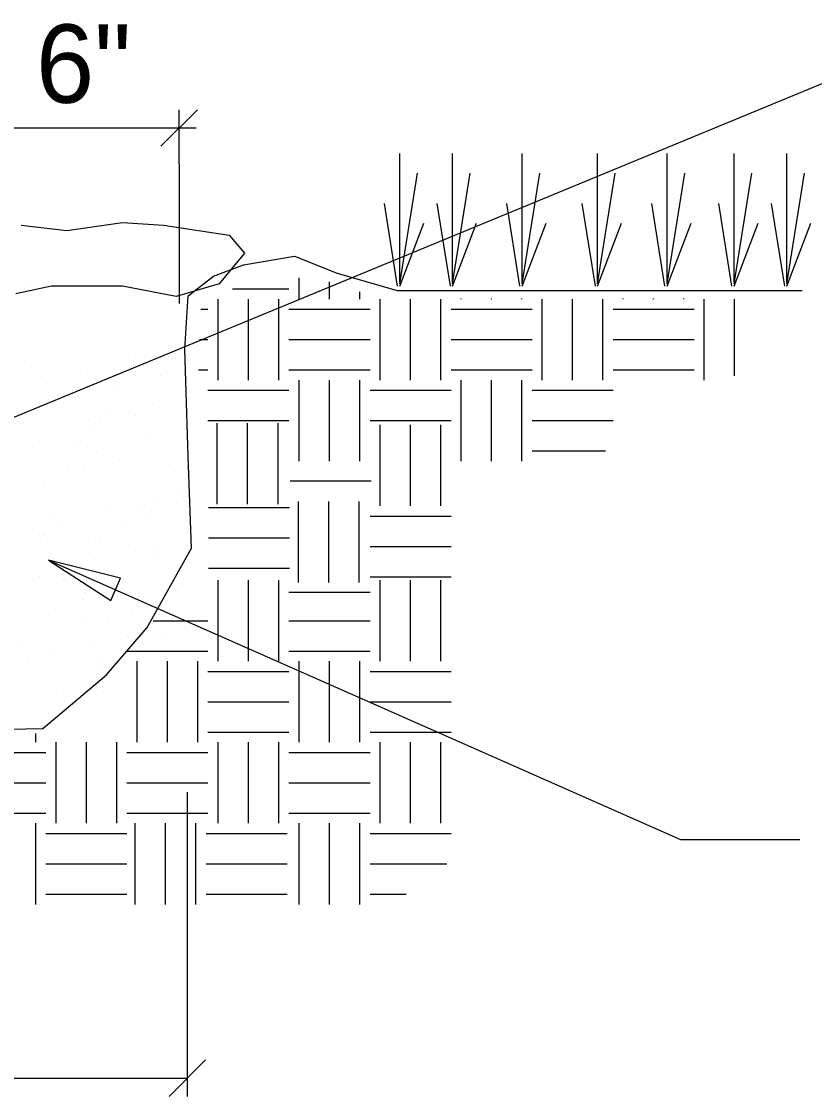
# Model space of a CAD drawing. Extents: x 10082 to 10186, y 10014 to 10052.
# Drawn here: x 10140.32 to 10147.41, y 10037.57 to 10047.18 of the extents above; entities that cross this region are included whole.
import ezdxf

# ---------------------------------------------------------------- set-up
doc = ezdxf.new("R2010")
doc.units = 0
for name, color, linetype in [('Default', 7, 'Continuous'), ('G-DETL-LINE', 7, 'Continuous'), ('G-DETL-OTLN', 7, 'Continuous'), ('G-DETL-PATT', 7, 'Continuous'), ('G-DETL-TEXT', 7, 'Continuous')]:
    doc.layers.add(name, color=color, linetype=linetype)

msp = doc.modelspace()

# ---------------------------------------------------------------- linework, layer by layer
at = {"layer": 'Default'}
for p, q in [((10148.8255, 10047.185), (10138.6003, 10042.9639)), ((10141.5679, 10046.0695), (10141.8951, 10046.3967)), ((10141.7315, 10045.9132), (10141.7315, 10046.3967)), ((10141.7315, 10045.9132), (10141.7315, 10044.6626)), ((10140.5637, 10042.3692), (10146.2107, 10039.8724)), ((10141.8034, 10040.2946), (10141.8034, 10037.5748)), ((10146.2107, 10039.8724), (10147.2796, 10039.8724)), ((10141.6398, 10037.5748), (10141.967, 10037.902)), ((10131.4864, 10037.7384), (10141.8034, 10037.7384))]:
    msp.add_line(p, q, dxfattribs=at)
msp.add_lwpolyline([(10139.3889, 10046.2331), (10141.8813, 10046.2331)], dxfattribs=at)
msp.add_lwpolyline([(10141.1194, 10042.009), (10141.2062, 10042.2087), (10140.5637, 10042.3692)], close=True, dxfattribs=at)
at = {"layer": 'G-DETL-LINE'}
for p, q in [((10143.7023, 10044.8565), (10143.7023, 10046.0061)), ((10144.1749, 10044.8565), (10144.1749, 10046.0061)), ((10144.7969, 10044.8565), (10144.7969, 10046.0061)), ((10145.4714, 10044.8565), (10145.4714, 10046.0061)), ((10146.0933, 10044.8565), (10146.0933, 10046.0061)), ((10146.6911, 10044.8565), (10146.6911, 10046.0061)), ((10147.1636, 10044.8565), (10147.1636, 10046.0061)), ((10143.7023, 10044.839), (10143.8599, 10045.8306)), ((10144.1749, 10044.839), (10144.3324, 10045.8306)), ((10144.7969, 10044.839), (10144.9544, 10045.8306)), ((10145.4714, 10044.839), (10145.6289, 10045.8306)), ((10146.0933, 10044.839), (10146.2509, 10045.8306)), ((10146.6911, 10044.839), (10146.8486, 10045.8306)), ((10147.1636, 10044.839), (10147.3212, 10045.8306)), ((10143.6821, 10044.8185), (10143.565, 10045.5586)), ((10144.1547, 10044.8185), (10144.0376, 10045.5586)), ((10144.7767, 10044.8185), (10144.6595, 10045.5586)), ((10145.4512, 10044.8185), (10145.334, 10045.5586)), ((10146.0731, 10044.8185), (10145.956, 10045.5586)), ((10146.6709, 10044.8185), (10146.5538, 10045.5586)), ((10147.1434, 10044.8185), (10147.0263, 10045.5586)), ((10143.7023, 10044.8185), (10143.9164, 10045.3831)), ((10144.1749, 10044.8185), (10144.3889, 10045.3831)), ((10144.7969, 10044.8185), (10145.0109, 10045.3831)), ((10145.4714, 10044.8185), (10145.6854, 10045.3831)), ((10146.0933, 10044.8185), (10146.3074, 10045.3831)), ((10146.6911, 10044.8185), (10146.9052, 10045.3831)), ((10147.1636, 10044.8185), (10147.3777, 10045.3831))]:
    msp.add_line(p, q, dxfattribs=at)
at = {"layer": 'G-DETL-OTLN'}
for points in [[(10140.3195, 10045.3656), (10140.7269, 10045.3179), (10141.2242, 10045.3873), (10141.5897, 10045.3656), (10142.1768, 10045.2745), (10142.3146, 10045.1139), (10142.0869, 10044.8405), (10141.7035, 10044.7277), (10141.2242, 10044.8189), (10140.5891, 10044.8189), (10140.2716, 10044.7494)], [(10130.2469, 10045.0867), (10130.8832, 10045.0749), (10131.3086, 10044.6496), (10131.3086, 10044.0551), (10131.2787, 10042.6449), (10131.6441, 10041.7684), (10132.2672, 10041.1175), (10133.142, 10040.8918), (10134.3821, 10040.8658), (10137.6294, 10040.8918), (10138.9894, 10040.8354), (10140.5112, 10040.8658), (10141.0804, 10041.3431), (10141.4459, 10041.7684), (10141.8413, 10042.4757), (10141.8113, 10043.2958), (10141.7814, 10044.2547), (10141.8113, 10044.7321), (10142.0367, 10044.9098)], [(10142.3048, 10045.0104), (10142.7621, 10045.0867)], [(10142.7621, 10045.0867), (10143.1432, 10044.9342)], [(10142.0367, 10044.9098), (10142.3048, 10045.0104)], [(10143.1432, 10044.9342), (10143.6797, 10044.7816)], [(10143.6797, 10044.7816), (10147.3002, 10044.7816)]]:
    msp.add_lwpolyline(points, dxfattribs=at)
at = {"layer": 'G-DETL-PATT'}
for p, q in [((10140.3704, 10044.8719), (10140.3704, 10044.8719)), ((10142.8029, 10044.7039), (10142.8029, 10044.8939)), ((10143.0745, 10044.7039), (10143.0745, 10044.8591)), ((10142.2079, 10044.7944), (10142.7124, 10044.7944)), ((10143.3461, 10044.7039), (10143.3461, 10044.7685)), ((10142.0787, 10043.9797), (10142.0787, 10044.7039)), ((10142.3503, 10043.9797), (10142.3503, 10044.7039)), ((10142.6219, 10043.9797), (10142.6219, 10044.7039)), ((10143.5272, 10043.9797), (10143.5272, 10044.7039)), ((10143.7988, 10043.9797), (10143.7988, 10044.7039)), ((10144.0704, 10043.9797), (10144.0704, 10044.7039)), ((10144.2514, 10044.7039), (10144.2514, 10044.7081)), ((10144.523, 10044.7039), (10144.523, 10044.7081)), ((10144.7946, 10044.7039), (10144.7946, 10044.7081)), ((10144.9757, 10043.9797), (10144.9757, 10044.7039)), ((10145.2472, 10043.9797), (10145.2472, 10044.7039)), ((10145.5188, 10043.9797), (10145.5188, 10044.7039)), ((10145.6999, 10044.7039), (10145.6999, 10044.7081)), ((10145.9715, 10044.7039), (10145.9715, 10044.7081)), ((10146.2431, 10044.7039), (10146.2431, 10044.7081)), ((10146.4241, 10043.9797), (10146.4241, 10044.7039)), ((10146.6957, 10044.0166), (10146.6957, 10044.7039)), ((10141.9229, 10044.6134), (10141.9882, 10044.6134)), ((10142.7124, 10044.6134), (10143.4366, 10044.6134)), ((10144.1609, 10044.6134), (10144.8851, 10044.6134)), ((10145.6094, 10044.6134), (10146.3336, 10044.6134)), ((10141.9129, 10044.3418), (10141.9882, 10044.3418)), ((10142.7124, 10044.3418), (10143.4366, 10044.3418)), ((10144.1609, 10044.3418), (10144.8851, 10044.3418)), ((10145.6094, 10044.3418), (10146.3336, 10044.3418)), ((10141.2734, 10044.1823), (10141.2734, 10044.1823)), ((10141.6387, 10044.1874), (10141.6387, 10044.1874)), ((10140.3468, 10044.1477), (10140.3468, 10044.1477)), ((10141.3929, 10044.1386), (10141.3929, 10044.1386)), ((10140.5018, 10044.0157), (10140.5018, 10044.0157)), ((10140.8466, 10044.0385), (10140.8466, 10044.0385)), ((10141.5624, 10044.0175), (10141.5624, 10044.0175)), ((10141.9029, 10044.0702), (10141.9882, 10044.0702)), ((10142.7124, 10044.0702), (10143.4366, 10044.0702)), ((10144.1609, 10044.0702), (10144.8851, 10044.0702)), ((10145.6094, 10044.0702), (10146.3336, 10044.0702)), ((10141.181, 10043.9053), (10141.181, 10043.9053)), ((10142.8029, 10043.2554), (10142.8029, 10043.9797)), ((10143.0745, 10043.2554), (10143.0745, 10043.9797)), ((10143.3461, 10043.2554), (10143.3461, 10043.9797)), ((10144.2514, 10043.2554), (10144.2514, 10043.9797)), ((10144.523, 10043.2554), (10144.523, 10043.9797)), ((10144.7946, 10043.2554), (10144.7946, 10043.9797)), ((10140.5623, 10043.8049), (10140.5623, 10043.8049)), ((10141.9882, 10043.8891), (10142.7124, 10043.8891)), ((10143.4366, 10043.8891), (10144.1609, 10043.8891)), ((10144.8851, 10043.8891), (10145.6094, 10043.8891)), ((10140.3496, 10043.7112), (10140.3496, 10043.7112)), ((10141.4939, 10043.7684), (10141.4939, 10043.7684)), ((10140.9243, 10043.6221), (10140.9243, 10043.6221)), ((10141.0199, 10043.6493), (10141.0199, 10043.6493)), ((10141.0755, 10043.6925), (10141.0755, 10043.6925)), ((10141.3389, 10043.6618), (10141.3389, 10043.6618)), ((10141.7763, 10043.6221), (10141.7763, 10043.6221)), ((10141.9882, 10043.6175), (10142.7124, 10043.6175)), ((10143.4366, 10043.6175), (10144.1609, 10043.6175)), ((10144.8851, 10043.6175), (10145.6094, 10043.6175)), ((10140.933, 10043.5532), (10140.933, 10043.5532)), ((10141.4358, 10043.5088), (10141.4358, 10043.5088)), ((10142.0713, 10042.8713), (10142.0713, 10043.5956)), ((10142.3429, 10042.8713), (10142.3429, 10043.5956)), ((10142.6145, 10042.8713), (10142.6145, 10043.5956)), ((10143.5272, 10042.854), (10143.5272, 10043.5782)), ((10143.7988, 10042.854), (10143.7988, 10043.5782)), ((10144.0704, 10042.854), (10144.0704, 10043.5782)), ((10140.421, 10043.3842), (10140.421, 10043.3842)), ((10140.7965, 10043.4007), (10140.7965, 10043.4007)), ((10140.911, 10043.3846), (10140.911, 10043.3846)), ((10140.9899, 10043.33), (10140.9899, 10043.33)), ((10141.8189, 10043.4007), (10141.8189, 10043.4007)), ((10144.8851, 10043.346), (10145.5419, 10043.346)), ((10141.1932, 10043.2601), (10141.1932, 10043.2601)), ((10140.7367, 10043.1967), (10140.7367, 10043.1967)), ((10140.8776, 10043.2027), (10140.8776, 10043.2027)), ((10141.6922, 10043.1664), (10141.6922, 10043.1664)), ((10140.5253, 10043.0661), (10140.5253, 10043.0661)), ((10142.7237, 10043.0776), (10143.4479, 10043.0776)), ((10141.7287, 10042.9493), (10141.7287, 10042.9493)), ((10141.1041, 10042.8427), (10141.1041, 10042.8427)), ((10141.3664, 10042.8709), (10141.3664, 10042.8709)), ((10141.4174, 10042.8551), (10141.4174, 10042.8551)), ((10141.5378, 10042.9238), (10141.5378, 10042.9238)), ((10141.705, 10042.8868), (10141.705, 10042.8868)), ((10141.9928, 10042.8415), (10142.717, 10042.8415)), ((10142.7962, 10042.1684), (10142.7962, 10042.8926)), ((10143.0678, 10042.1684), (10143.0678, 10042.8926)), ((10143.3394, 10042.1684), (10143.3394, 10042.8926)), ((10143.4366, 10042.7634), (10144.1609, 10042.7634)), ((10140.5835, 10042.7366), (10140.5835, 10042.7366)), ((10140.6797, 10042.7129), (10140.6797, 10042.7129)), ((10141.2225, 10042.6628), (10141.2225, 10042.6628)), ((10141.4355, 10042.7366), (10141.4355, 10042.7366)), ((10140.4173, 10042.6425), (10140.4173, 10042.6425)), ((10140.5229, 10042.5886), (10140.5229, 10042.5886)), ((10141.9928, 10042.57), (10142.717, 10042.57)), ((10140.4943, 10042.5322), (10140.4943, 10042.5322)), ((10140.9865, 10042.5321), (10140.9865, 10042.5321)), ((10141.0197, 10042.5284), (10141.0197, 10042.5284)), ((10141.3431, 10042.4579), (10141.3431, 10042.4579)), ((10141.5397, 10042.4818), (10141.5397, 10042.4818)), ((10143.4366, 10042.4918), (10144.1609, 10042.4918)), ((10140.9715, 10042.3777), (10140.9715, 10042.3777)), ((10141.5071, 10042.397), (10141.5071, 10042.397)), ((10141.9928, 10042.2984), (10142.717, 10042.2984)), ((10140.4818, 10042.2231), (10140.4818, 10042.2231)), ((10140.6961, 10042.1994), (10140.6961, 10042.1994)), ((10140.8449, 10042.1677), (10140.8449, 10042.1677)), ((10142.0787, 10041.4654), (10142.0787, 10042.1896)), ((10142.3503, 10041.4654), (10142.3503, 10042.1896)), ((10142.6219, 10041.4654), (10142.6219, 10042.1896)), ((10143.4366, 10042.2203), (10144.1609, 10042.2203)), ((10143.5272, 10041.4654), (10143.5272, 10042.1896)), ((10143.7988, 10041.4654), (10143.7988, 10042.1896)), ((10144.0704, 10041.4654), (10144.0704, 10042.1896)), ((10140.8821, 10042.0845), (10140.8821, 10042.0845)), ((10141.713, 10042.0926), (10141.713, 10042.0926)), ((10142.7124, 10042.0835), (10143.4366, 10042.0835)), ((10140.8692, 10042.0237), (10140.8692, 10042.0237)), ((10140.6261, 10041.9249), (10140.6261, 10041.9249)), ((10141.3092, 10041.9072), (10141.3092, 10041.9072)), ((10141.6485, 10041.9249), (10141.6485, 10041.9249)), ((10140.8694, 10041.8103), (10140.8694, 10041.8103)), ((10141.0947, 10041.8512), (10141.0947, 10041.8512)), ((10141.4973, 10041.8275), (10141.9882, 10041.8275)), ((10142.7124, 10041.8275), (10143.4366, 10041.8275)), ((10141.2725, 10041.6928), (10141.2725, 10041.6928)), ((10140.3344, 10041.6102), (10140.3344, 10041.6102)), ((10140.9264, 10041.6055), (10140.9264, 10041.6055)), ((10141.6183, 10041.6726), (10141.6183, 10041.6726)), ((10140.6035, 10041.548), (10140.6035, 10041.548)), ((10141.0401, 10041.5111), (10141.0401, 10041.5111)), ((10141.2064, 10041.5586), (10141.2064, 10041.5586)), ((10141.2639, 10041.5559), (10141.9882, 10041.5559)), ((10142.7124, 10041.5559), (10143.4366, 10041.5559)), ((10140.3724, 10041.4829), (10140.3724, 10041.4829)), ((10141.0427, 10041.4211), (10141.0427, 10041.4211)), ((10141.1113, 10041.4174), (10141.1113, 10041.4174)), ((10141.3545, 10040.7412), (10141.3545, 10041.4654)), ((10141.6261, 10040.7412), (10141.6261, 10041.4654)), ((10141.6264, 10041.452), (10141.6264, 10041.452)), ((10141.8976, 10040.7412), (10141.8976, 10041.4654)), ((10142.8029, 10040.7412), (10142.8029, 10041.4654)), ((10143.0745, 10040.7412), (10143.0745, 10041.4654)), ((10143.3461, 10040.7412), (10143.3461, 10041.4654)), ((10141.9882, 10041.3749), (10142.7124, 10041.3749)), ((10143.4366, 10041.3749), (10144.1609, 10041.3749)), ((10140.6344, 10041.2047), (10140.6344, 10041.2047)), ((10141.0521, 10041.1871), (10141.0521, 10041.1871)), ((10141.9882, 10041.1033), (10142.7124, 10041.1033)), ((10143.4366, 10041.1033), (10144.1609, 10041.1033)), ((10140.4492, 10040.7412), (10140.4492, 10040.8207)), ((10141.9882, 10040.8317), (10142.7124, 10040.8317)), ((10143.4366, 10040.8317), (10144.1609, 10040.8317)), ((10140.6302, 10040.0169), (10140.6302, 10040.7412)), ((10140.9018, 10040.0169), (10140.9018, 10040.7412)), ((10141.1734, 10040.0169), (10141.1734, 10040.7412)), ((10142.0787, 10040.0169), (10142.0787, 10040.7412)), ((10142.3503, 10040.0169), (10142.3503, 10040.7412)), ((10142.6219, 10040.0169), (10142.6219, 10040.7412)), ((10143.5272, 10040.0169), (10143.5272, 10040.7412)), ((10143.7988, 10040.0169), (10143.7988, 10040.7412)), ((10144.0704, 10040.0169), (10144.0704, 10040.7412)), ((10139.8155, 10040.6506), (10140.5397, 10040.6506)), ((10141.2639, 10040.6506), (10141.9882, 10040.6506)), ((10142.7124, 10040.6506), (10143.4366, 10040.6506)), ((10139.8155, 10040.3791), (10140.5397, 10040.3791)), ((10141.2639, 10040.3791), (10141.9882, 10040.3791)), ((10142.7124, 10040.3791), (10143.4366, 10040.3791)), ((10139.8155, 10040.1075), (10140.5397, 10040.1075)), ((10141.2639, 10040.1075), (10141.9882, 10040.1075)), ((10142.7124, 10040.1075), (10143.4366, 10040.1075)), ((10140.4492, 10039.2927), (10140.4492, 10040.0169)), ((10141.3369, 10039.2927), (10141.3369, 10040.0169)), ((10141.6085, 10039.2927), (10141.6085, 10040.0169)), ((10141.8801, 10039.2927), (10141.8801, 10040.0169)), ((10142.8029, 10039.2927), (10142.8029, 10040.0169)), ((10143.0745, 10039.2927), (10143.0745, 10040.0169)), ((10143.3461, 10039.2927), (10143.3461, 10040.0169)), ((10140.5397, 10039.9264), (10141.2639, 10039.9264)), ((10141.9706, 10039.9264), (10142.6948, 10039.9264)), ((10143.4366, 10039.9264), (10144.1609, 10039.9264)), ((10140.5397, 10039.6548), (10141.2639, 10039.6548)), ((10141.9706, 10039.6548), (10142.6948, 10039.6548)), ((10143.4366, 10039.6548), (10144.1223, 10039.6548)), ((10140.5397, 10039.3832), (10141.2639, 10039.3832)), ((10141.9706, 10039.3832), (10142.6948, 10039.3832)), ((10143.4366, 10039.3832), (10143.7605, 10039.3832))]:
    msp.add_line(p, q, dxfattribs=at)

# ---------------------------------------------------------------- texts
at = {"layer": 'G-DETL-TEXT'}
msp.add_text('6"', height=0.7, dxfattribs=at).set_placement((10140.4505, 10046.4586))

doc.saveas('drawing.dxf')
